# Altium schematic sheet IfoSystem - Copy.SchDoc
size C; Engineer: Daniel Sigg; DocumentNumber: 2; SheetNumber: 2; SheetTotal: 8
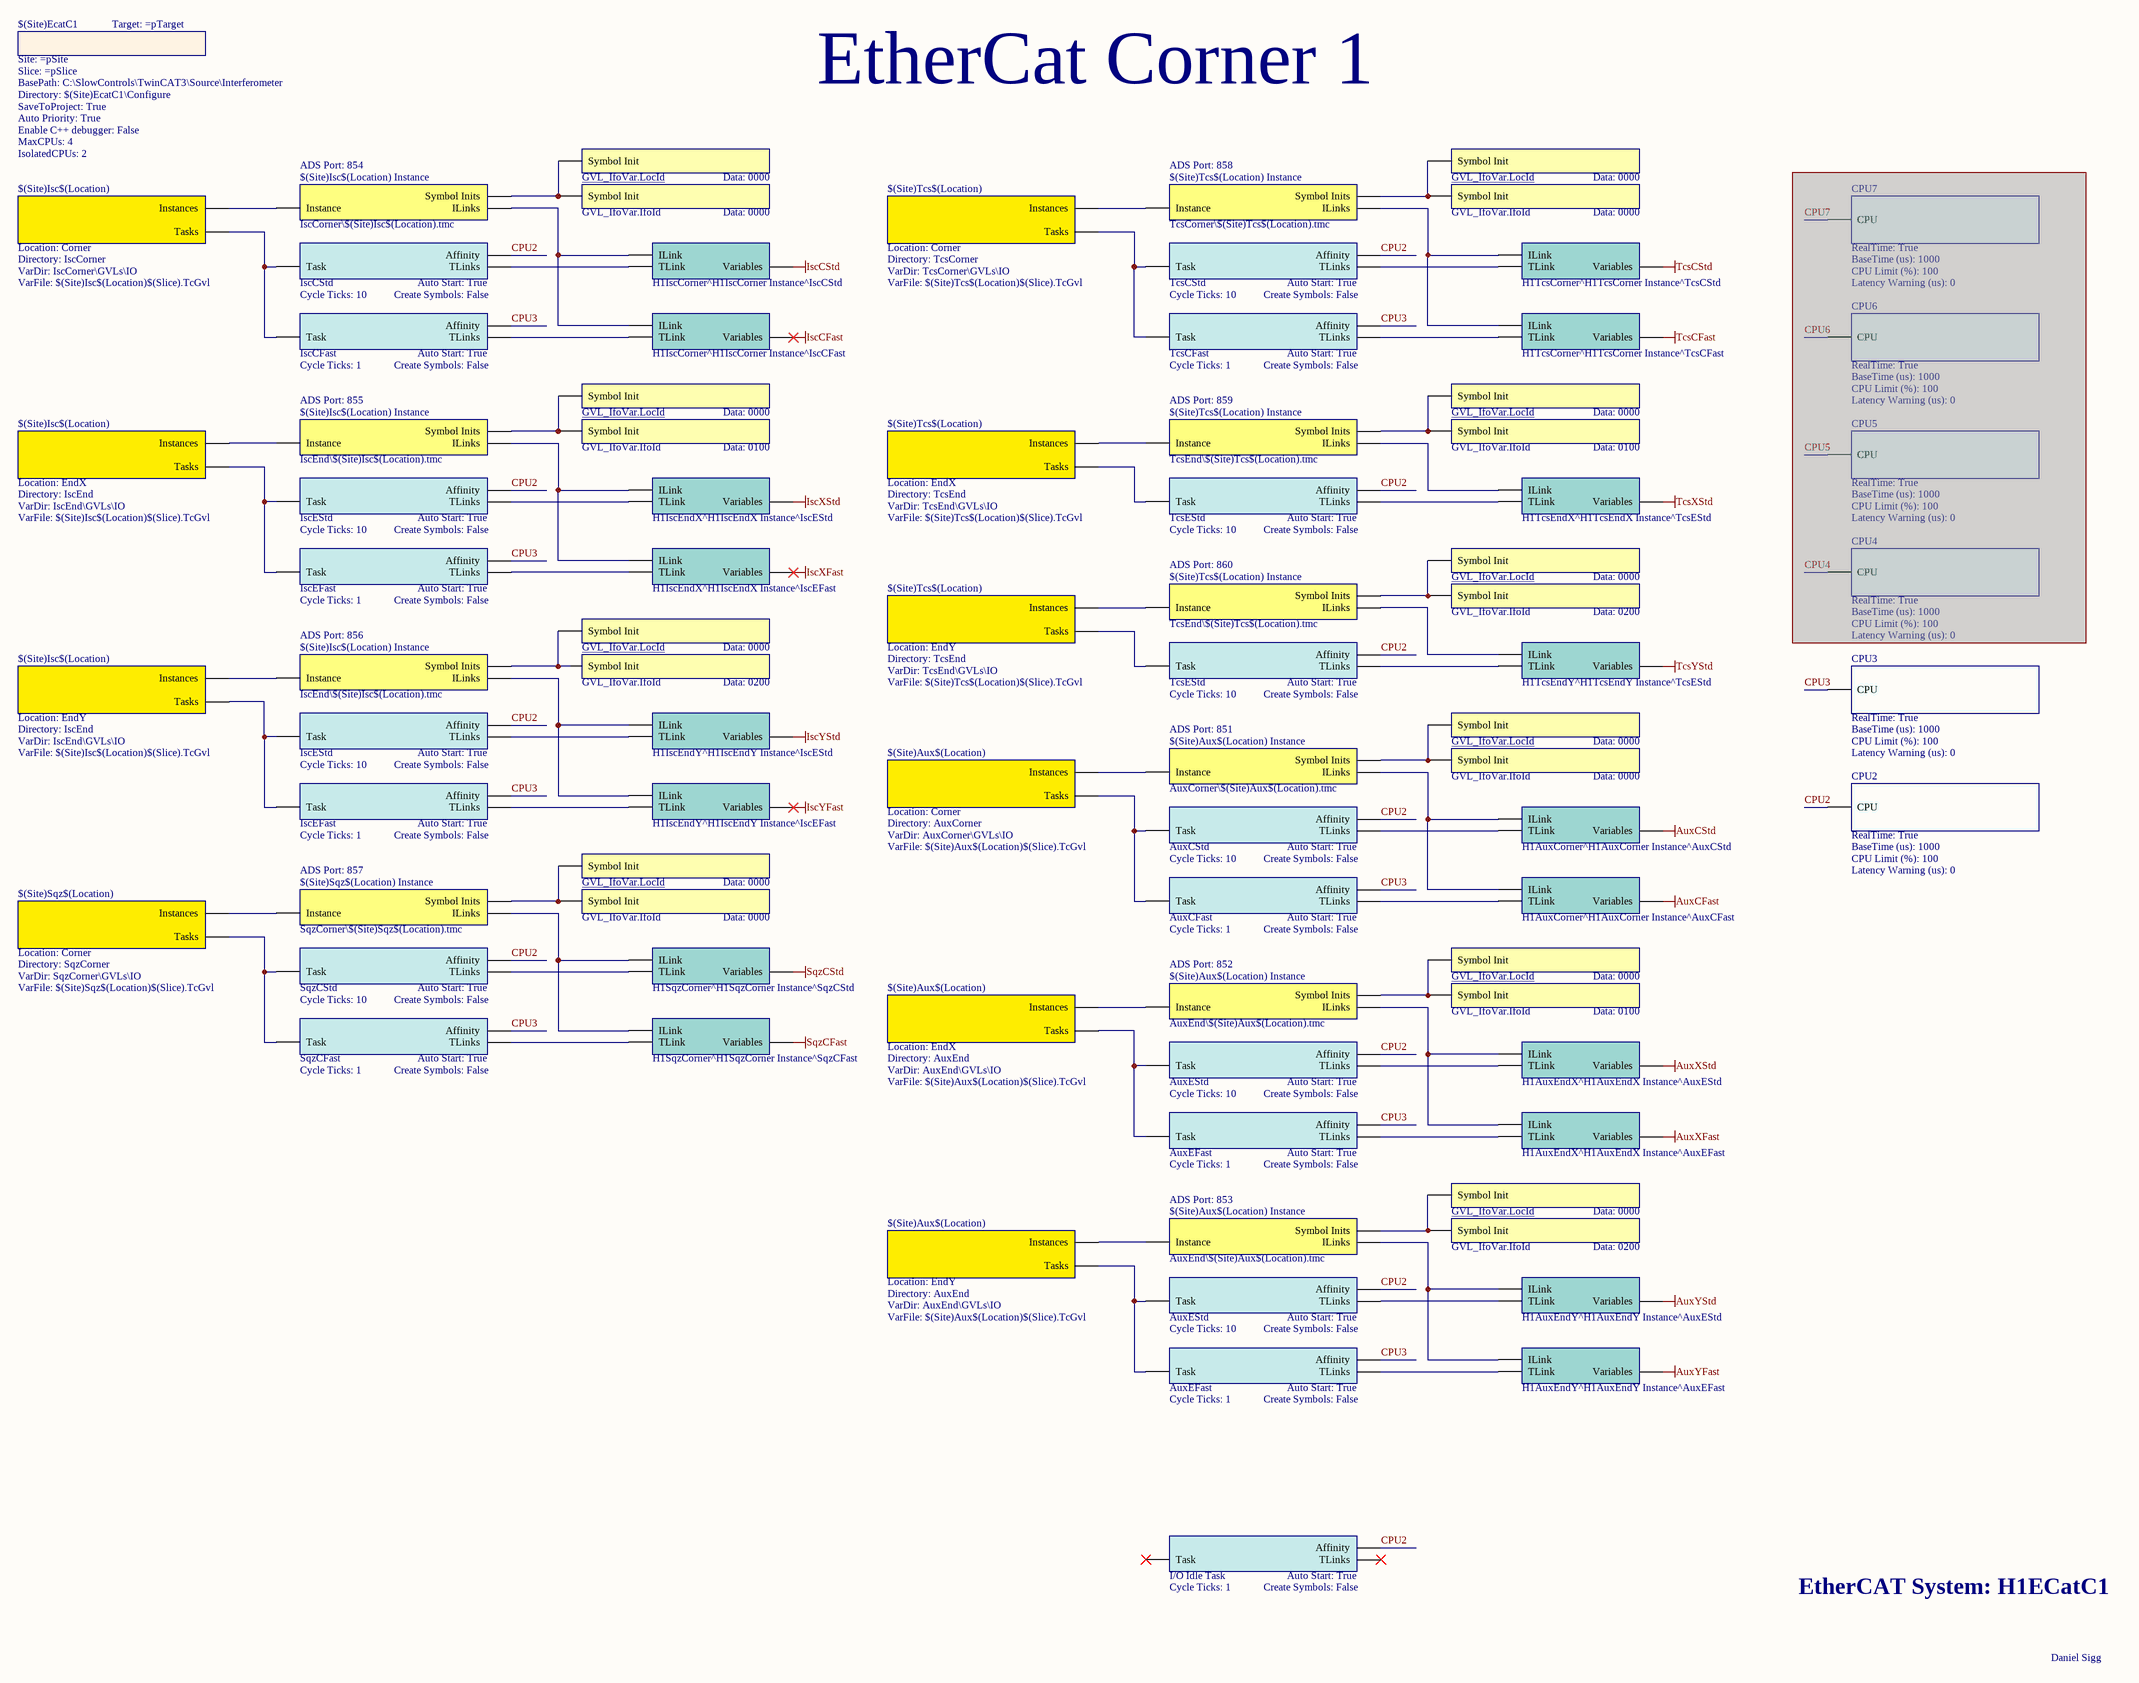
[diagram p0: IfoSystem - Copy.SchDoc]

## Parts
CPU2  RealTime: True  BaseTime (us): 1000  CPU Limit (%): 100  Latency Warning (us): 0  (hidden comment: CPU)  (mechanical)
CPU3  RealTime: True  BaseTime (us): 1000  CPU Limit (%): 100  Latency Warning (us): 0  (hidden comment: CPU)  (mechanical)
CPU4  RealTime: True  BaseTime (us): 1000  CPU Limit (%): 100  Latency Warning (us): 0  (hidden comment: CPU)  (mechanical)  (masked out: inside a compile mask, not in the netlist)
CPU5  RealTime: True  BaseTime (us): 1000  CPU Limit (%): 100  Latency Warning (us): 0  (hidden comment: CPU)  (mechanical)  (masked out: inside a compile mask, not in the netlist)
CPU6  RealTime: True  BaseTime (us): 1000  CPU Limit (%): 100  Latency Warning (us): 0  (hidden comment: CPU)  (mechanical)  (masked out: inside a compile mask, not in the netlist)
CPU7  RealTime: True  BaseTime (us): 1000  CPU Limit (%): 100  Latency Warning (us): 0  (hidden comment: CPU)  (mechanical)  (masked out: inside a compile mask, not in the netlist)
I1  $(Site)Isc$(Location) Instance  ADS Port: 854  Filename: IscCorner\$(Site)Isc$(Location).tmc  (mechanical)
I2  $(Site)Isc$(Location) Instance  ADS Port: 855  Filename: IscEnd\$(Site)Isc$(Location).tmc  (mechanical)
I3  $(Site)Isc$(Location) Instance  ADS Port: 856  Filename: IscEnd\$(Site)Isc$(Location).tmc  (mechanical)
I4  $(Site)Sqz$(Location) Instance  ADS Port: 857  Filename: SqzCorner\$(Site)Sqz$(Location).tmc  (mechanical)
I5  $(Site)Tcs$(Location) Instance  ADS Port: 858  Filename: TcsCorner\$(Site)Tcs$(Location).tmc  (mechanical)
I6  $(Site)Tcs$(Location) Instance  ADS Port: 859  Filename: TcsEnd\$(Site)Tcs$(Location).tmc  (mechanical)
I7  $(Site)Tcs$(Location) Instance  ADS Port: 860  Filename: TcsEnd\$(Site)Tcs$(Location).tmc  (mechanical)
I8  $(Site)Aux$(Location) Instance  ADS Port: 851  Filename: AuxCorner\$(Site)Aux$(Location).tmc  (mechanical)
I9  $(Site)Aux$(Location) Instance  ADS Port: 852  Filename: AuxEnd\$(Site)Aux$(Location).tmc  (mechanical)
I10  $(Site)Aux$(Location) Instance  ADS Port: 853  Filename: AuxEnd\$(Site)Aux$(Location).tmc  (mechanical)
PLC1  $(Site)Isc$(Location)  Directory: IscCorner  Location: Corner  VarFile: $(Site)Isc$(Location)$(Slice).TcGvl  VarDir: IscCorner\GVLs\IO  (mechanical)
PLC2  $(Site)Isc$(Location)  Directory: IscEnd  Location: EndX  VarFile: $(Site)Isc$(Location)$(Slice).TcGvl  VarDir: IscEnd\GVLs\IO  (mechanical)
PLC3  $(Site)Isc$(Location)  Directory: IscEnd  Location: EndY  VarFile: $(Site)Isc$(Location)$(Slice).TcGvl  VarDir: IscEnd\GVLs\IO  (mechanical)
PLC4  $(Site)Sqz$(Location)  Directory: SqzCorner  Location: Corner  VarFile: $(Site)Sqz$(Location)$(Slice).TcGvl  VarDir: SqzCorner\GVLs\IO  (mechanical)
PLC5  $(Site)Tcs$(Location)  Directory: TcsCorner  Location: Corner  VarFile: $(Site)Tcs$(Location)$(Slice).TcGvl  VarDir: TcsCorner\GVLs\IO  (mechanical)
PLC6  $(Site)Tcs$(Location)  Directory: TcsEnd  Location: EndX  VarFile: $(Site)Tcs$(Location)$(Slice).TcGvl  VarDir: TcsEnd\GVLs\IO  (mechanical)
PLC7  $(Site)Tcs$(Location)  Directory: TcsEnd  Location: EndY  VarFile: $(Site)Tcs$(Location)$(Slice).TcGvl  VarDir: TcsEnd\GVLs\IO  (mechanical)
PLC8  $(Site)Aux$(Location)  Directory: AuxCorner  Location: Corner  VarFile: $(Site)Aux$(Location)$(Slice).TcGvl  VarDir: AuxCorner\GVLs\IO  (mechanical)
PLC9  $(Site)Aux$(Location)  Directory: AuxEnd  Location: EndX  VarFile: $(Site)Aux$(Location)$(Slice).TcGvl  VarDir: AuxEnd\GVLs\IO  (mechanical)
PLC10  $(Site)Aux$(Location)  Directory: AuxEnd  Location: EndY  VarFile: $(Site)Aux$(Location)$(Slice).TcGvl  VarDir: AuxEnd\GVLs\IO  (mechanical)
S1  GVL_IfoVar.LocId  Data: 0000  (mechanical)
S2  GVL_IfoVar.IfoId  Data: 0000  (mechanical)
S3  GVL_IfoVar.LocId  Data: 0000  (mechanical)
S4  GVL_IfoVar.IfoId  Data: 0100  (mechanical)
S5  GVL_IfoVar.LocId  Data: 0000  (mechanical)
S6  GVL_IfoVar.IfoId  Data: 0200  (mechanical)
S7  GVL_IfoVar.LocId  Data: 0000  (mechanical)
S8  GVL_IfoVar.IfoId  Data: 0000  (mechanical)
S9  GVL_IfoVar.LocId  Data: 0000  (mechanical)
S10  GVL_IfoVar.IfoId  Data: 0000  (mechanical)
S11  GVL_IfoVar.LocId  Data: 0000  (mechanical)
S12  GVL_IfoVar.IfoId  Data: 0100  (mechanical)
S13  GVL_IfoVar.LocId  Data: 0000  (mechanical)
S14  GVL_IfoVar.IfoId  Data: 0200  (mechanical)
S15  GVL_IfoVar.LocId  Data: 0000  (mechanical)
S16  GVL_IfoVar.IfoId  Data: 0000  (mechanical)
S17  GVL_IfoVar.LocId  Data: 0000  (mechanical)
S18  GVL_IfoVar.IfoId  Data: 0100  (mechanical)
S19  GVL_IfoVar.LocId  Data: 0000  (mechanical)
S20  GVL_IfoVar.IfoId  Data: 0200  (mechanical)
System  $(Site)EcatC1  Auto Priority: True  Enable C++ debugger: False  Directory: $(Site)EcatC1\Configure  MaxCPUs: 4  IsolatedCPUs: 2  BasePath: C:\SlowControls\TwinCAT3\Source\Interferometer  (mechanical)
T1  IscCStd  Cycle Ticks: 10  Auto Start: True  Create Symbols: False  (mechanical)
T2  IscCFast  Cycle Ticks: 1  Auto Start: True  Create Symbols: False  (mechanical)
T3  IscEStd  Cycle Ticks: 10  Auto Start: True  Create Symbols: False  (mechanical)
T4  IscEFast  Cycle Ticks: 1  Auto Start: True  Create Symbols: False  (mechanical)
T5  IscEStd  Cycle Ticks: 10  Auto Start: True  Create Symbols: False  (mechanical)
T6  IscEFast  Cycle Ticks: 1  Auto Start: True  Create Symbols: False  (mechanical)
T7  SqzCStd  Cycle Ticks: 10  Auto Start: True  Create Symbols: False  (mechanical)
T8  SqzCFast  Cycle Ticks: 1  Auto Start: True  Create Symbols: False  (mechanical)
T9  H1IscCorner^H1IscCorner Instance^IscCStd  (mechanical)
T10  H1IscCorner^H1IscCorner Instance^IscCFast  (mechanical)
T11  H1IscEndX^H1IscEndX Instance^IscEStd  (mechanical)
T12  H1IscEndX^H1IscEndX Instance^IscEFast  (mechanical)
T13  H1IscEndY^H1IscEndY Instance^IscEStd  (mechanical)
T14  H1IscEndY^H1IscEndY Instance^IscEFast  (mechanical)
T15  H1SqzCorner^H1SqzCorner Instance^SqzCStd  (mechanical)
T16  H1SqzCorner^H1SqzCorner Instance^SqzCFast  (mechanical)
T17  TcsCStd  Cycle Ticks: 10  Auto Start: True  Create Symbols: False  (mechanical)
T18  TcsEStd  Cycle Ticks: 10  Auto Start: True  Create Symbols: False  (mechanical)
T19  TcsEStd  Cycle Ticks: 10  Auto Start: True  Create Symbols: False  (mechanical)
T20  AuxCStd  Cycle Ticks: 10  Auto Start: True  Create Symbols: False  (mechanical)
T21  AuxCFast  Cycle Ticks: 1  Auto Start: True  Create Symbols: False  (mechanical)
T22  AuxEStd  Cycle Ticks: 10  Auto Start: True  Create Symbols: False  (mechanical)
T23  AuxEFast  Cycle Ticks: 1  Auto Start: True  Create Symbols: False  (mechanical)
T24  AuxEStd  Cycle Ticks: 10  Auto Start: True  Create Symbols: False  (mechanical)
T25  AuxEFast  Cycle Ticks: 1  Auto Start: True  Create Symbols: False  (mechanical)
T26  I/O Idle Task  Cycle Ticks: 1  Auto Start: True  Create Symbols: False  (mechanical)
T27  H1TcsCorner^H1TcsCorner Instance^TcsCStd  (mechanical)
T28  H1TcsEndX^H1TcsEndX Instance^TcsEStd  (mechanical)
T29  H1TcsEndY^H1TcsEndY Instance^TcsEStd  (mechanical)
T30  H1AuxCorner^H1AuxCorner Instance^AuxCStd  (mechanical)
T31  H1AuxCorner^H1AuxCorner Instance^AuxCFast  (mechanical)
T32  H1AuxEndX^H1AuxEndX Instance^AuxEStd  (mechanical)
T33  H1AuxEndX^H1AuxEndX Instance^AuxEFast  (mechanical)
T34  H1AuxEndY^H1AuxEndY Instance^AuxEStd  (mechanical)
T35  H1AuxEndY^H1AuxEndY Instance^AuxEFast  (mechanical)
T36  TcsCFast  Cycle Ticks: 1  Auto Start: True  Create Symbols: False  (mechanical)
T37  H1TcsCorner^H1TcsCorner Instance^TcsCFast  (mechanical)

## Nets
AuxCFast: T31.0(Variables)
AuxCStd: T30.0(Variables)
AuxXFast: T33.0(Variables)
AuxXStd: T32.0(Variables)
AuxYFast: T35.0(Variables)
AuxYStd: T34.0(Variables)
IscCFast: T10.0(Variables)
IscCStd: T9.0(Variables)
IscXFast: T12.0(Variables)
IscXStd: T11.0(Variables)
IscYFast: T14.0(Variables)
IscYStd: T13.0(Variables)
SqzCFast: T16.0(Variables)
SqzCStd: T15.0(Variables)
TcsCFast: T37.0(Variables)
TcsCStd: T27.0(Variables)
TcsXStd: T28.0(Variables)
TcsYStd: T29.0(Variables)
CPU2: CPU2.0(CPU) T1.1(Affinity) T3.1(Affinity) T5.1(Affinity) T7.1(Affinity) T17.1(Affinity) T18.1(Affinity) T19.1(Affinity) T20.1(Affinity) T22.1(Affinity) T24.1(Affinity) T26.1(Affinity)
CPU3: CPU3.0(CPU) T2.1(Affinity) T4.1(Affinity) T6.1(Affinity) T8.1(Affinity) T21.1(Affinity) T23.1(Affinity) T25.1(Affinity) T36.1(Affinity)
NetI1_0: I1.0(Instance) PLC1.0(Instances)
NetI1_2: I1.2(ILinks) T9.1(ILink) T10.1(ILink)
NetI1_2: I1.2(Symbol_Inits) S1.99(Symbol_Init) S2.99(Symbol_Init)  [a separate net that carries the same name]
NetI2_0: I2.0(Instance) PLC2.0(Instances)
NetI2_2: I2.2(ILinks) T11.1(ILink) T12.1(ILink)
NetI2_2: I2.2(Symbol_Inits) S3.99(Symbol_Init) S4.99(Symbol_Init)  [a separate net that carries the same name]
NetI3_0: I3.0(Instance) PLC3.0(Instances)
NetI3_2: I3.2(ILinks) T13.1(ILink) T14.1(ILink)
NetI3_2: I3.2(Symbol_Inits) S5.99(Symbol_Init) S6.99(Symbol_Init)  [a separate net that carries the same name]
NetI4_0: I4.0(Instance) PLC4.0(Instances)
NetI4_2: I4.2(ILinks) T15.1(ILink) T16.1(ILink)
NetI4_2: I4.2(Symbol_Inits) S7.99(Symbol_Init) S8.99(Symbol_Init)  [a separate net that carries the same name]
NetI5_0: I5.0(Instance) PLC5.0(Instances)
NetI5_2: I5.2(Symbol_Inits) S9.99(Symbol_Init) S10.99(Symbol_Init)
NetI5_2: I5.2(ILinks) T27.1(ILink) T37.1(ILink)  [a separate net that carries the same name]
NetI6_0: I6.0(Instance) PLC6.0(Instances)
NetI6_2: I6.2(ILinks) T28.1(ILink)
NetI6_2: I6.2(Symbol_Inits) S11.99(Symbol_Init) S12.99(Symbol_Init)  [a separate net that carries the same name]
NetI7_0: I7.0(Instance) PLC7.0(Instances)
NetI7_2: I7.2(ILinks) T29.1(ILink)
NetI7_2: I7.2(Symbol_Inits) S13.99(Symbol_Init) S14.99(Symbol_Init)  [a separate net that carries the same name]
NetI8_0: I8.0(Instance) PLC8.0(Instances)
NetI8_2: I8.2(ILinks) T30.1(ILink) T31.1(ILink)
NetI8_2: I8.2(Symbol_Inits) S15.99(Symbol_Init) S16.99(Symbol_Init)  [a separate net that carries the same name]
NetI9_0: I9.0(Instance) PLC9.0(Instances)
NetI9_2: I9.2(ILinks) T32.1(ILink) T33.1(ILink)
NetI9_2: I9.2(Symbol_Inits) S17.99(Symbol_Init) S18.99(Symbol_Init)  [a separate net that carries the same name]
NetI10_0: I10.0(Instance) PLC10.0(Instances)
NetI10_2: I10.2(ILinks) T34.1(ILink) T35.1(ILink)
NetI10_2: I10.2(Symbol_Inits) S19.99(Symbol_Init) S20.99(Symbol_Init)  [a separate net that carries the same name]
NetPLC1_1: PLC1.1(Tasks) T1.0(Task) T2.0(Task)
NetPLC2_1: PLC2.1(Tasks) T3.0(Task) T4.0(Task)
NetPLC3_1: PLC3.1(Tasks) T5.0(Task) T6.0(Task)
NetPLC4_1: PLC4.1(Tasks) T7.0(Task) T8.0(Task)
NetPLC5_1: PLC5.1(Tasks) T17.0(Task) T36.0(Task)
NetPLC6_1: PLC6.1(Tasks) T18.0(Task)
NetPLC7_1: PLC7.1(Tasks) T19.0(Task)
NetPLC8_1: PLC8.1(Tasks) T20.0(Task) T21.0(Task)
NetPLC9_1: PLC9.1(Tasks) T22.0(Task) T23.0(Task)
NetPLC10_1: PLC10.1(Tasks) T24.0(Task) T25.0(Task)
NetT1_2: T1.2(TLinks) T9.2(TLink)
NetT2_2: T2.2(TLinks) T10.2(TLink)
NetT3_2: T3.2(TLinks) T11.2(TLink)
NetT4_2: T4.2(TLinks) T12.2(TLink)
NetT5_2: T5.2(TLinks) T13.2(TLink)
NetT6_2: T6.2(TLinks) T14.2(TLink)
NetT7_2: T7.2(TLinks) T15.2(TLink)
NetT8_2: T8.2(TLinks) T16.2(TLink)
NetT17_2: T17.2(TLinks) T27.2(TLink)
NetT18_2: T18.2(TLinks) T28.2(TLink)
NetT19_2: T19.2(TLinks) T29.2(TLink)
NetT20_2: T20.2(TLinks) T30.2(TLink)
NetT21_2: T21.2(TLinks) T31.2(TLink)
NetT22_2: T22.2(TLinks) T32.2(TLink)
NetT23_2: T23.2(TLinks) T33.2(TLink)
NetT24_2: T24.2(TLinks) T34.2(TLink)
NetT25_2: T25.2(TLinks) T35.2(TLink)
NetT36_2: T36.2(TLinks) T37.2(TLink)

Not connected (* = marked no-connect by the designer): T26 0(Task)* 2(TLinks)*

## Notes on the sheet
- EtherCat Corner 1
- EtherCAT System: H1ECatC1
- Daniel Sigg

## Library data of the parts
CPU2-CPU7 = TwinCATCPU: TwinCAT CPU
I1 = TwinCATInstance: TwinCAT PLC Instance; Symbol Init: QOGVYBPF; PLC: H1IscCorner; Location: Corner
I2 = TwinCATInstance: TwinCAT PLC Instance; Symbol Init: ANWTYMNB; PLC: H1IscEndX; Location: EndX
I3 = TwinCATInstance: TwinCAT PLC Instance; Symbol Init: TKQDQPCD; PLC: H1IscEndY; Location: EndY
I4 = TwinCATInstance: TwinCAT PLC Instance; Symbol Init: JDCVMCFT; PLC: H1SqzCorner; Location: Corner
I5 = TwinCATInstance: TwinCAT PLC Instance; Symbol Init: PQEEGHBX; PLC: H1TcsCorner; Location: Corner
I6 = TwinCATInstance: TwinCAT PLC Instance; Symbol Init: PMAHGRIT; PLC: H1TcsEndX; Location: EndX
I7 = TwinCATInstance: TwinCAT PLC Instance; Symbol Init: QCDHSLLL; PLC: H1TcsEndY; Location: EndY
I8 = TwinCATInstance: TwinCAT PLC Instance; Symbol Init: FOFYGOIF; PLC: H1AuxCorner; Location: Corner
I9 = TwinCATInstance: TwinCAT PLC Instance; Symbol Init: VPBKJCNL; PLC: H1AuxEndX; Location: EndX
I10 = TwinCATInstance: TwinCAT PLC Instance; Symbol Init: HWRHWHNB; PLC: H1AuxEndY; Location: EndY
PLC1 = TwinCATPLC: TwinCAT PLC; Instance: GYFKFSOI; GuidAux: F7B73D3F-0700-4170-B081-51FF7E74E11C; GuidIsc: D1956509-5744-43F3-9B7B-D941F72C7FB9; GuidSqz: E8509F6F-DE7B-406F-BE1C-8E2946DAF127; GuidEndX: B785F8B9-E13B-4D2F-9EF0-D6AF56071E69; GuidEndY: dc1ca917-7493-45bf-b3d0-84a754d6d4aa
PLC2 = TwinCATPLC: TwinCAT PLC; Instance: EWVUFOBF; GuidAux: 6F9BFA80-4189-43BE-BDFC-EBE047FD14BE; GuidIsc: 22C06909-20FD-40E9-81B1-45F4B7825166; GuidSqz: A7C15E78-97D2-4042-A877-8FC051EE60F0; GuidEndX: 941CBAEC-0E75-4DD6-83B0-4CD68B52537A; GuidEndY: BAB03BEF-674E-49DB-A1B7-57B4D2FBC53F
PLC3 = TwinCATPLC: TwinCAT PLC; Instance: NJXXMYFB; GuidAux: 4232AA5C-5848-47FE-955C-D987CC1FDFED; GuidIsc: 9F8D78B8-710A-45B6-A613-C69C109DC6AE; GuidSqz: CFBA572B-0EFB-4F30-8336-9EA3BFE213B0; GuidEndX: C8FF922A-8B74-4506-A05D-1015046E3DE4; GuidEndY: DA69B215-ED13-4B16-8D77-5E6CBD3F326E
PLC4 = TwinCATPLC: TwinCAT PLC; Instance: GIVXPOYF; GuidAux: A9450A75-5FBE-4AC4-997D-15A20D20792C; GuidIsc: 481FCBAD-5251-4DDF-8BA5-DC20A5EBF994; GuidSqz: 6899C224-C27B-4763-ACB7-CC14C145D099; GuidEndX: E2B06DF2-5E44-4E68-98F8-C1974B9BA949; GuidEndY: 95996F75-DE58-4C2C-B45A-797BA61A5D1F
PLC5 = TwinCATPLC: TwinCAT PLC; Instance: MUFDHMNW; GuidAux: C50FA94B-48B7-4438-9044-14E2324B6BC8; GuidIsc: A5A7D8D2-E044-4246-88AE-75408302B269; GuidSqz: 07EF5EDE-9623-44C4-83DA-86990748EA32; GuidEndX: 83FEEC08-2C7D-4A84-8FAB-C6036137B0FD; GuidEndY: 848253A1-597B-4453-9F36-E80FE499DBE9
PLC6 = TwinCATPLC: TwinCAT PLC; Instance: TPTTRFUS; GuidAux: 45895ECC-B09C-4816-9B69-02A97A864656; GuidIsc: 3B00533A-5978-43DF-A8E2-C397ABAF0EEE; GuidSqz: 85E4F5E2-8F7A-4E79-9040-7EA68824E8B5; GuidEndX: 1FC4E3D0-5DC9-450A-969E-BDE61855525C; GuidEndY: 7F07F7BD-E183-4ECC-A7DE-78A78E90DD77
PLC7 = TwinCATPLC: TwinCAT PLC; Instance: BORUSAKV; GuidAux: 3B473438-D344-4AA1-8776-9256BDF220B9; GuidIsc: 6BAB2067-AB72-4B3C-8D54-2E4A2B2837D2; GuidSqz: 10FCE1BF-5528-47F0-A046-1BEBBC5F2661; GuidEndX: 6A53364E-1F24-4E8E-BFEB-F55D104A475B; GuidEndY: 31C085AE-C640-4CD1-A7A7-6BA129779F58
PLC8 = TwinCATPLC: TwinCAT PLC; Instance: FFXNWLLD; GuidAux: B56CB62D-6451-4F1A-B8F0-CB22CD3E26CE; GuidIsc: 3407FA45-B350-45A5-B540-766593F62C6F; GuidSqz: FE01CD8C-4049-4F4D-B86A-16A75D7BE085; GuidEndX: BEC0E448-2132-47B9-961F-6E85A9686312; GuidEndY: B5BE63F5-ABE3-4FB9-A52D-5B46DAA1161C
PLC9 = TwinCATPLC: TwinCAT PLC; Instance: NTIEJDWE; GuidAux: 46E871D2-F470-43FC-91C0-283C5668EAD1; GuidIsc: 4E8A81B2-28C8-4D9B-836D-30DEE990E112; GuidSqz: A37AD24F-B0F0-4BB2-83A6-361870006908; GuidEndX: 96E7C0E1-F97A-43E6-B125-913655A3ABA1; GuidEndY: 8F4E714F-B84D-486A-9BB2-E66C9F94A24C
PLC10 = TwinCATPLC: TwinCAT PLC; Instance: KMWKGJTW; GuidAux: 590C2516-4440-4FC4-B72B-2617DDFAC970; GuidIsc: 2EA1D704-5084-475D-8D2D-A124DA0702E8; GuidSqz: 20CC2962-7C21-4198-B030-226935B89024; GuidEndX: 355B4D47-6EDC-438E-B8BD-D4BAA8F06B39; GuidEndY: FACD52A0-3B0D-4056-81F7-0A977E3E633B
S1 = TwinCATSymbol: TwinCAT Symbol Initialization; Next: KBGCXKHJ
S2 S4 S6 S8 S10 S12 S14 S16 S18 S20 = TwinCATSymbol: TwinCAT Symbol Initialization
S3 = TwinCATSymbol: TwinCAT Symbol Initialization; Next: RFHBSAYS
S5 = TwinCATSymbol: TwinCAT Symbol Initialization; Next: YLQCSWVN
S7 = TwinCATSymbol: TwinCAT Symbol Initialization; Next: LKBTSDNS
S9 = TwinCATSymbol: TwinCAT Symbol Initialization; Next: FADMXHAG
S11 = TwinCATSymbol: TwinCAT Symbol Initialization; Next: OKYYBMVQ
S13 = TwinCATSymbol: TwinCAT Symbol Initialization; Next: JGJNILQS
S15 = TwinCATSymbol: TwinCAT Symbol Initialization; Next: FCGACHJI
S17 = TwinCATSymbol: TwinCAT Symbol Initialization; Next: SEHPMEBM
S19 = TwinCATSymbol: TwinCAT Symbol Initialization; Next: LHVAWOAX
System = TwinCATSystem: TwinCAT System
T1 T3 T5 T7 T17-T20 T22 T24 T26 = TwinCATTask: TwinCAT Task; CPU: 2; BaseTime (100ns): 10000
T2 T4 T6 T8 T21 T23 T25 T36 = TwinCATTask: TwinCAT Task; CPU: 3; BaseTime (100ns): 10000
T9-T16 T27-T35 T37 = TwinCATLink: TwinCAT Variable Link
